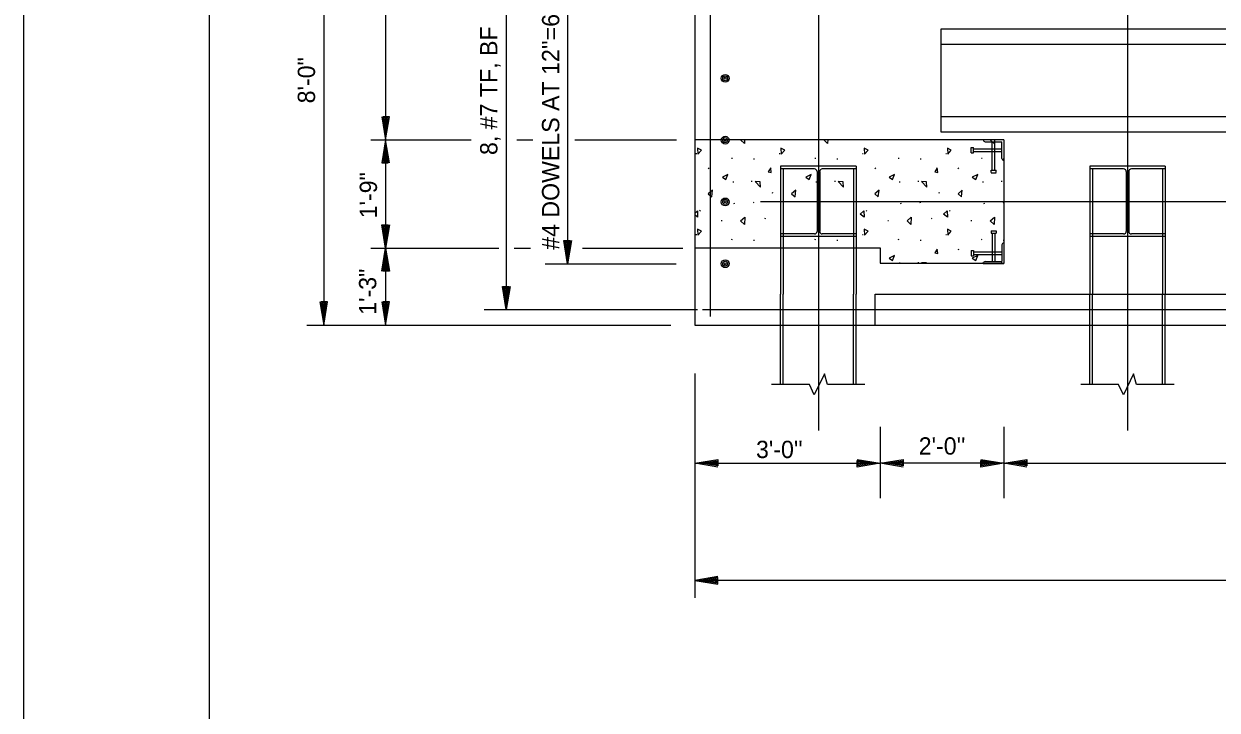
# Model space of a CAD drawing. Extents: x -11983 to -11903, y -13969.5 to -13913.5.
# Drawn here: x -11983.01 to -11963.71, y -13935.3 to -13924.19 of the extents above; entities that cross this region are included whole.
import ezdxf

# ---------------------------------------------------------------- set-up
doc = ezdxf.new("R2010")
doc.units = 0
for name, color, linetype in [('Level 1', 7, 'Continuous'), ('Level 2', 7, 'Continuous'), ('Level 22', 7, 'Continuous'), ('Level 25', 7, 'Continuous'), ('Level 3', 7, 'Continuous'), ('Level 44', 7, 'Continuous'), ('Level 50', 7, 'Continuous'), ('Level 6', 7, 'Continuous')]:
    doc.layers.add(name, color=color, linetype=linetype)

msp = doc.modelspace()

# ---------------------------------------------------------------- linework, layer by layer
at = {"layer": 'Level 1'}
for points in [[(-11983.012, -13913.481), (-11903.012, -13913.481), (-11903.012, -13969.481), (-11983.012, -13969.481)], [(-11980.012, -13914.481), (-11904.012, -13914.481), (-11904.012, -13968.481), (-11980.012, -13968.481)]]:
    msp.add_lwpolyline(points, close=True, dxfattribs=at)
at = {"layer": 'Level 2'}
for p, q in [((-11972.163, -13921.074), (-11972.163, -13929.066)), ((-11968.183, -13924.274), (-11942.163, -13924.274)), ((-11968.183, -13924.279), (-11968.183, -13925.941)), ((-11968.183, -13924.524), (-11942.122, -13924.524)), ((-11968.183, -13925.691), (-11942.122, -13925.691)), ((-11968.183, -13925.941), (-11942.163, -13925.941)), ((-11972.163, -13926.066), (-11967.163, -13926.066)), ((-11967.496, -13926.07), (-11967.496, -13926.07)), ((-11967.465, -13926.102), (-11967.195, -13926.102)), ((-11967.351, -13926.56), (-11967.351, -13926.102)), ((-11967.309, -13926.56), (-11967.309, -13926.102)), ((-11967.195, -13926.372), (-11967.195, -13926.102)), ((-11967.163, -13926.07), (-11967.163, -13928.066)), ((-11967.163, -13926.07), (-11967.163, -13926.403)), ((-11967.694, -13926.278), (-11967.694, -13926.195)), ((-11967.694, -13926.195), (-11967.653, -13926.195)), ((-11967.694, -13926.278), (-11967.653, -13926.278)), ((-11967.653, -13926.278), (-11967.653, -13926.195)), ((-11967.653, -13926.216), (-11967.195, -13926.216)), ((-11967.653, -13926.258), (-11967.195, -13926.258)), ((-11969.554, -13926.498), (-11970.773, -13926.498)), ((-11970.773, -13926.498), (-11970.773, -13926.54)), ((-11970.773, -13926.54), (-11970.773, -13928.566)), ((-11970.226, -13926.54), (-11970.773, -13926.54)), ((-11970.731, -13926.54), (-11970.731, -13928.566)), ((-11969.554, -13926.54), (-11970.101, -13926.54)), ((-11969.596, -13926.54), (-11969.596, -13928.566)), ((-11969.554, -13926.498), (-11969.554, -13926.54)), ((-11969.554, -13926.54), (-11969.554, -13928.566)), ((-11967.371, -13926.56), (-11967.288, -13926.56)), ((-11967.371, -13926.599), (-11967.371, -13926.56)), ((-11967.288, -13926.599), (-11967.288, -13926.56)), ((-11967.163, -13926.403), (-11967.163, -13926.403)), ((-11967.163, -13926.403), (-11967.163, -13927.737)), ((-11964.554, -13926.498), (-11965.773, -13926.498)), ((-11965.773, -13926.498), (-11965.773, -13926.54)), ((-11965.773, -13926.54), (-11965.773, -13928.566)), ((-11965.226, -13926.54), (-11965.773, -13926.54)), ((-11965.731, -13926.54), (-11965.731, -13928.566)), ((-11964.554, -13926.54), (-11965.101, -13926.54)), ((-11964.596, -13926.54), (-11964.596, -13928.566)), ((-11964.554, -13926.498), (-11964.554, -13926.54)), ((-11964.554, -13926.54), (-11964.554, -13928.566)), ((-11970.184, -13926.582), (-11970.184, -13927.55)), ((-11970.142, -13926.582), (-11970.142, -13927.55)), ((-11967.371, -13926.601), (-11967.288, -13926.601)), ((-11965.184, -13926.582), (-11965.184, -13927.55)), ((-11965.142, -13926.582), (-11965.142, -13927.55)), ((-11970.226, -13927.592), (-11970.773, -13927.592)), ((-11970.773, -13927.592), (-11970.773, -13927.634)), ((-11969.554, -13927.634), (-11970.773, -13927.634)), ((-11969.554, -13927.592), (-11970.101, -13927.592)), ((-11969.554, -13927.592), (-11969.554, -13927.634)), ((-11967.371, -13927.54), (-11967.288, -13927.54)), ((-11967.371, -13927.541), (-11967.371, -13927.581)), ((-11967.371, -13927.581), (-11967.288, -13927.581)), ((-11967.351, -13927.581), (-11967.351, -13928.039)), ((-11967.309, -13927.581), (-11967.309, -13928.039)), ((-11967.288, -13927.541), (-11967.288, -13927.581)), ((-11965.226, -13927.592), (-11965.773, -13927.592)), ((-11965.773, -13927.592), (-11965.773, -13927.634)), ((-11964.554, -13927.634), (-11965.773, -13927.634)), ((-11964.554, -13927.592), (-11965.101, -13927.592)), ((-11964.554, -13927.592), (-11964.554, -13927.634)), ((-11972.163, -13927.816), (-11969.163, -13927.816)), ((-11969.163, -13927.816), (-11969.163, -13928.066)), ((-11967.694, -13927.862), (-11967.694, -13927.945)), ((-11967.694, -13927.862), (-11967.653, -13927.862)), ((-11967.653, -13927.862), (-11967.653, -13927.945)), ((-11967.653, -13927.883), (-11967.195, -13927.883)), ((-11967.195, -13927.769), (-11967.195, -13928.039)), ((-11967.163, -13927.737), (-11967.163, -13927.737)), ((-11967.163, -13927.737), (-11967.163, -13928.07)), ((-11969.163, -13928.066), (-11967.163, -13928.066)), ((-11967.694, -13927.945), (-11967.653, -13927.945)), ((-11967.653, -13927.925), (-11967.195, -13927.925)), ((-11967.496, -13928.07), (-11967.496, -13928.07)), ((-11967.465, -13928.039), (-11967.195, -13928.039)), ((-11970.773, -13930.027), (-11970.773, -13928.566)), ((-11970.731, -13930.027), (-11970.731, -13928.566)), ((-11969.596, -13930.027), (-11969.596, -13928.566)), ((-11969.554, -13930.027), (-11969.554, -13928.566)), ((-11969.243, -13928.566), (-11957.178, -13928.566)), ((-11969.243, -13929.066), (-11969.243, -13928.566)), ((-11965.773, -13930.027), (-11965.773, -13928.566)), ((-11965.731, -13930.027), (-11965.731, -13928.566)), ((-11964.596, -13930.027), (-11964.596, -13928.566)), ((-11964.554, -13930.027), (-11964.554, -13928.566)), ((-11972.163, -13929.066), (-11957.178, -13929.066)), ((-11971.163, -13929.066), (-11965.413, -13929.066)), ((-11970.309, -13930.027), (-11970.919, -13930.027)), ((-11970.229, -13930.194), (-11970.309, -13930.027)), ((-11970.066, -13929.857), (-11970.229, -13930.194)), ((-11970.018, -13930.027), (-11970.066, -13929.857)), ((-11969.41, -13930.027), (-11970.018, -13930.027)), ((-11965.309, -13930.027), (-11965.919, -13930.027)), ((-11965.229, -13930.194), (-11965.309, -13930.027)), ((-11965.066, -13929.857), (-11965.229, -13930.194)), ((-11965.018, -13930.027), (-11965.066, -13929.857)), ((-11964.41, -13930.027), (-11965.018, -13930.027))]:
    msp.add_line(p, q, dxfattribs=at)
for centre, radius, start, end in [((-11967.465, -13926.07), 0.0312, 180, 270), ((-11967.163, -13926.372), 0.0312, 180, 270), ((-11970.226, -13926.582), 0.0417, 0, 90), ((-11970.101, -13926.582), 0.0417, 90, 180), ((-11965.226, -13926.582), 0.0417, 0, 90), ((-11965.101, -13926.582), 0.0417, 90, 180), ((-11970.226, -13927.55), 0.0417, 270, 0), ((-11970.101, -13927.55), 0.0417, 180, 270), ((-11965.226, -13927.55), 0.0417, 270, 0), ((-11965.101, -13927.55), 0.0417, 180, 270), ((-11967.163, -13927.769), 0.0312, 90, 180), ((-11967.465, -13928.07), 0.0312, 90, 180)]:
    msp.add_arc(centre, radius, start, end, dxfattribs=at)
at = {"layer": 'Level 22'}
for p, q in [((-11975.21, -13921.321), (-11975.21, -13928.814)), ((-11974.22, -13922.074), (-11974.22, -13928.074)), ((-11970.163, -13926.377), (-11970.163, -13927.066)), ((-11965.163, -13926.377), (-11965.163, -13927.066)), ((-11970.163, -13927.066), (-11970.163, -13927.857)), ((-11965.163, -13927.066), (-11965.163, -13927.857)), ((-11969.163, -13930.71), (-11969.163, -13931.868)), ((-11967.163, -13930.71), (-11967.163, -13931.868)), ((-11967.163, -13931.302), (-11969.163, -13931.302))]:
    msp.add_line(p, q, dxfattribs=at)
at = {"layer": 'Level 25'}
msp.add_line((-11967.496, -13928.07), (-11967.163, -13928.07), dxfattribs=at)
at = {"layer": 'Level 3'}
for p, q in [((-11978.163, -13921.074), (-11978.163, -13929.066)), ((-11977.163, -13921.074), (-11977.163, -13926.07)), ((-11970.163, -13923.074), (-11970.163, -13927.066)), ((-11965.163, -13923.074), (-11965.163, -13927.066)), ((-11977.163, -13924.57), (-11977.163, -13926.568)), ((-11977.163, -13925.966), (-11977.163, -13925.966)), ((-11977.403, -13926.07), (-11975.779, -13926.07)), ((-11977.163, -13926.07), (-11977.163, -13926.07)), ((-11977.163, -13926.07), (-11977.163, -13926.07)), ((-11977.163, -13926.07), (-11977.163, -13927.82)), ((-11977.163, -13926.174), (-11977.163, -13926.174)), ((-11975.042, -13926.07), (-11974.779, -13926.07)), ((-11974.102, -13926.07), (-11972.455, -13926.07)), ((-11971.099, -13927.066), (-11955.163, -13927.066)), ((-11970.163, -13927.066), (-11970.163, -13930.77)), ((-11970.163, -13927.066), (-11970.163, -13930.77)), ((-11965.163, -13927.066), (-11965.163, -13930.77)), ((-11977.403, -13927.82), (-11975.331, -13927.82)), ((-11977.163, -13927.82), (-11977.163, -13929.066)), ((-11975.085, -13927.82), (-11974.819, -13927.82)), ((-11973.975, -13927.82), (-11972.356, -13927.82)), ((-11974.581, -13928.074), (-11972.465, -13928.074)), ((-11975.567, -13928.814), (-11972.12, -13928.814)), ((-11978.435, -13929.066), (-11972.547, -13929.066)), ((-11978.163, -13928.962), (-11978.163, -13928.962)), ((-11978.163, -13929.066), (-11978.163, -13929.066)), ((-11977.163, -13928.962), (-11977.163, -13928.962)), ((-11977.163, -13929.066), (-11977.163, -13929.066)), ((-11972.163, -13929.85), (-11972.163, -13932.694)), ((-11972.163, -13930.824), (-11972.163, -13933.48)), ((-11972.163, -13931.302), (-11969.163, -13931.302)), ((-11967.163, -13931.302), (-11943.125, -13931.302)), ((-11938.163, -13933.196), (-11972.163, -13933.196)), ((-11972.163, -13933.196), (-11972.163, -13933.196)), ((-11972.059, -13933.196), (-11972.059, -13933.196))]:
    msp.add_line(p, q, dxfattribs=at)
for points in [[(-11977.225, -13925.696), (-11977.163, -13926.07), (-11977.101, -13925.696), (-11977.207, -13925.696), (-11977.163, -13925.966), (-11977.121, -13925.712), (-11977.189, -13925.712), (-11977.163, -13925.866), (-11977.141, -13925.728), (-11977.169, -13925.728), (-11977.163, -13925.762)], [(-11977.101, -13926.444), (-11977.163, -13926.07), (-11977.225, -13926.444), (-11977.119, -13926.444), (-11977.163, -13926.174), (-11977.205, -13926.428), (-11977.137, -13926.428), (-11977.163, -13926.274), (-11977.185, -13926.412), (-11977.157, -13926.412), (-11977.163, -13926.378)], [(-11978.225, -13928.692), (-11978.163, -13929.066), (-11978.101, -13928.692), (-11978.207, -13928.692), (-11978.163, -13928.962), (-11978.121, -13928.708), (-11978.189, -13928.708), (-11978.163, -13928.862), (-11978.141, -13928.724), (-11978.169, -13928.724), (-11978.163, -13928.758)], [(-11977.225, -13928.692), (-11977.163, -13929.066), (-11977.101, -13928.692), (-11977.207, -13928.692), (-11977.163, -13928.962), (-11977.121, -13928.708), (-11977.189, -13928.708), (-11977.163, -13928.862), (-11977.141, -13928.724), (-11977.169, -13928.724), (-11977.163, -13928.758)], [(-11971.789, -13933.134), (-11972.163, -13933.196), (-11971.789, -13933.258), (-11971.789, -13933.152), (-11972.059, -13933.196), (-11971.805, -13933.238), (-11971.805, -13933.17), (-11971.959, -13933.196), (-11971.821, -13933.218), (-11971.821, -13933.19), (-11971.855, -13933.196)]]:
    msp.add_lwpolyline(points, dxfattribs=at)
at = {"layer": 'Level 44'}
for p, q in [((-11971.721, -13926.068), (-11971.735, -13926.07)), ((-11970.374, -13926.068), (-11970.389, -13926.07)), ((-11967.681, -13926.068), (-11967.695, -13926.07)), ((-11972.13, -13926.295), (-11972.143, -13926.294)), ((-11971.552, -13926.373), (-11971.566, -13926.371)), ((-11970.783, -13926.295), (-11970.797, -13926.294)), ((-11970.206, -13926.373), (-11970.219, -13926.371)), ((-11969.437, -13926.295), (-11969.45, -13926.294)), ((-11968.859, -13926.373), (-11968.872, -13926.371)), ((-11968.09, -13926.295), (-11968.103, -13926.294)), ((-11967.548, -13926.22), (-11967.566, -13926.22)), ((-11967.512, -13926.373), (-11967.526, -13926.371)), ((-11971.93, -13926.53), (-11971.946, -13926.538)), ((-11971.194, -13926.385), (-11971.212, -13926.385)), ((-11969.847, -13926.385), (-11969.865, -13926.385)), ((-11969.236, -13926.53), (-11969.252, -13926.538)), ((-11968.5, -13926.385), (-11968.518, -13926.385)), ((-11967.89, -13926.53), (-11967.906, -13926.538)), ((-11967.163, -13926.385), (-11967.172, -13926.385)), ((-11971.531, -13926.752), (-11971.549, -13926.752)), ((-11971.232, -13926.745), (-11971.249, -13926.745)), ((-11970.184, -13926.752), (-11970.202, -13926.752)), ((-11969.886, -13926.745), (-11969.903, -13926.745)), ((-11968.838, -13926.752), (-11968.856, -13926.752)), ((-11968.539, -13926.745), (-11968.556, -13926.745)), ((-11967.491, -13926.752), (-11967.509, -13926.752)), ((-11967.192, -13926.745), (-11967.209, -13926.745)), ((-11970.893, -13926.932), (-11970.91, -13926.929)), ((-11968.2, -13926.932), (-11968.217, -13926.929)), ((-11971.517, -13927.101), (-11971.535, -13927.106)), ((-11971.206, -13927.083), (-11971.219, -13927.088)), ((-11968.823, -13927.101), (-11968.841, -13927.106)), ((-11968.513, -13927.083), (-11968.526, -13927.088)), ((-11967.477, -13927.101), (-11967.495, -13927.106)), ((-11967.166, -13927.083), (-11967.179, -13927.088)), ((-11972.07, -13927.224), (-11972.085, -13927.215)), ((-11969.377, -13927.224), (-11969.392, -13927.215)), ((-11968.03, -13927.224), (-11968.045, -13927.215)), ((-11971.721, -13927.38), (-11971.735, -13927.381)), ((-11971.014, -13927.348), (-11971.028, -13927.341)), ((-11969.027, -13927.38), (-11969.042, -13927.381)), ((-11968.32, -13927.348), (-11968.335, -13927.341)), ((-11967.681, -13927.38), (-11967.695, -13927.381)), ((-11972.13, -13927.607), (-11972.143, -13927.606)), ((-11971.552, -13927.685), (-11971.566, -13927.683)), ((-11971.194, -13927.696), (-11971.212, -13927.696)), ((-11970.206, -13927.685), (-11970.219, -13927.683)), ((-11969.847, -13927.696), (-11969.865, -13927.696)), ((-11969.437, -13927.607), (-11969.45, -13927.606)), ((-11968.859, -13927.685), (-11968.872, -13927.683)), ((-11968.5, -13927.696), (-11968.518, -13927.696)), ((-11968.09, -13927.607), (-11968.103, -13927.606)), ((-11967.512, -13927.685), (-11967.526, -13927.683)), ((-11967.163, -13927.696), (-11967.172, -13927.696)), ((-11967.89, -13927.842), (-11967.906, -13927.85)), ((-11968.838, -13928.063), (-11968.856, -13928.063)), ((-11968.539, -13928.057), (-11968.556, -13928.057)), ((-11967.491, -13928.063), (-11967.509, -13928.063)), ((-11967.192, -13928.057), (-11967.209, -13928.057))]:
    msp.add_line(p, q, dxfattribs=at)
for points in [[(-11971.357, -13926.066), (-11971.36, -13926.127), (-11971.422, -13926.07), (-11971.417, -13926.066)], [(-11970.01, -13926.066), (-11970.014, -13926.127), (-11970.075, -13926.07), (-11970.071, -13926.066)], [(-11967.317, -13926.066), (-11967.32, -13926.127), (-11967.382, -13926.07), (-11967.377, -13926.066)], [(-11972.163, -13927.254), (-11972.12, -13927.216), (-11972.117, -13927.318), (-11972.163, -13927.284)], [(-11968.414, -13928.066), (-11968.414, -13928.061), (-11968.494, -13928.057), (-11968.485, -13928.066)]]:
    msp.add_lwpolyline(points, dxfattribs=at)
for points in [[(-11972.111, -13926.3), (-11972.054, -13926.236), (-11972.117, -13926.202)], [(-11970.764, -13926.3), (-11970.707, -13926.236), (-11970.771, -13926.202)], [(-11969.417, -13926.3), (-11969.36, -13926.236), (-11969.424, -13926.202)], [(-11968.071, -13926.3), (-11968.014, -13926.236), (-11968.077, -13926.202)], [(-11970.924, -13926.598), (-11970.934, -13926.525), (-11970.975, -13926.586)], [(-11968.231, -13926.598), (-11968.24, -13926.525), (-11968.281, -13926.586)], [(-11971.657, -13926.713), (-11971.625, -13926.631), (-11971.714, -13926.674)], [(-11971.107, -13926.75), (-11971.187, -13926.745), (-11971.101, -13926.834)], [(-11970.31, -13926.713), (-11970.279, -13926.631), (-11970.367, -13926.674)], [(-11969.761, -13926.75), (-11969.841, -13926.745), (-11969.754, -13926.834)], [(-11968.964, -13926.713), (-11968.932, -13926.631), (-11969.02, -13926.674)], [(-11968.414, -13926.75), (-11968.494, -13926.745), (-11968.407, -13926.834)], [(-11967.617, -13926.713), (-11967.585, -13926.631), (-11967.674, -13926.674)], [(-11971.876, -13926.884), (-11971.944, -13926.943), (-11971.887, -13926.991)], [(-11970.529, -13926.884), (-11970.597, -13926.943), (-11970.541, -13926.991)], [(-11969.182, -13926.884), (-11969.251, -13926.943), (-11969.194, -13926.991)], [(-11967.836, -13926.884), (-11967.904, -13926.943), (-11967.847, -13926.991)], [(-11971.36, -13927.439), (-11971.422, -13927.382), (-11971.354, -13927.321)], [(-11969.424, -13927.318), (-11969.488, -13927.27), (-11969.427, -13927.216)], [(-11968.667, -13927.439), (-11968.729, -13927.382), (-11968.66, -13927.321)], [(-11968.077, -13927.318), (-11968.141, -13927.27), (-11968.08, -13927.216)], [(-11967.32, -13927.439), (-11967.382, -13927.382), (-11967.314, -13927.321)], [(-11972.111, -13927.612), (-11972.054, -13927.548), (-11972.117, -13927.514)], [(-11969.417, -13927.612), (-11969.36, -13927.548), (-11969.424, -13927.514)], [(-11968.071, -13927.612), (-11968.014, -13927.548), (-11968.077, -13927.514)], [(-11968.231, -13927.91), (-11968.24, -13927.837), (-11968.281, -13927.898)], [(-11968.964, -13928.024), (-11968.932, -13927.943), (-11969.02, -13927.986)], [(-11967.617, -13928.024), (-11967.585, -13927.943), (-11967.674, -13927.986)]]:
    msp.add_lwpolyline(points, close=True, dxfattribs=at)
at = {"layer": 'Level 50'}
for p, q in [((-11977.163, -13927.716), (-11977.163, -13927.716)), ((-11977.163, -13927.82), (-11977.163, -13927.82)), ((-11977.163, -13927.82), (-11977.163, -13927.82)), ((-11977.163, -13927.924), (-11977.163, -13927.924)), ((-11974.22, -13927.97), (-11974.22, -13927.97)), ((-11974.22, -13928.074), (-11974.22, -13928.074)), ((-11975.21, -13928.71), (-11975.21, -13928.71)), ((-11975.21, -13928.814), (-11975.21, -13928.814)), ((-11972.163, -13931.302), (-11972.163, -13931.302)), ((-11972.059, -13931.302), (-11972.059, -13931.302)), ((-11969.267, -13931.302), (-11969.267, -13931.302)), ((-11969.163, -13931.302), (-11969.163, -13931.302)), ((-11969.163, -13931.302), (-11969.163, -13931.302)), ((-11969.059, -13931.302), (-11969.059, -13931.302)), ((-11967.267, -13931.302), (-11967.267, -13931.302)), ((-11967.163, -13931.302), (-11967.163, -13931.302)), ((-11967.163, -13931.302), (-11967.163, -13931.302)), ((-11967.059, -13931.302), (-11967.059, -13931.302))]:
    msp.add_line(p, q, dxfattribs=at)
for points in [[(-11977.101, -13927.446), (-11977.163, -13927.82), (-11977.225, -13927.446), (-11977.119, -13927.446), (-11977.163, -13927.716), (-11977.205, -13927.462), (-11977.137, -13927.462), (-11977.163, -13927.616), (-11977.185, -13927.478), (-11977.157, -13927.478), (-11977.163, -13927.512)], [(-11974.158, -13927.7), (-11974.22, -13928.074), (-11974.282, -13927.7), (-11974.176, -13927.7), (-11974.22, -13927.97), (-11974.262, -13927.716), (-11974.194, -13927.716), (-11974.22, -13927.87), (-11974.242, -13927.732), (-11974.214, -13927.732), (-11974.22, -13927.766)], [(-11977.225, -13928.194), (-11977.163, -13927.82), (-11977.101, -13928.194), (-11977.207, -13928.194), (-11977.163, -13927.924), (-11977.121, -13928.178), (-11977.189, -13928.178), (-11977.163, -13928.024), (-11977.141, -13928.162), (-11977.169, -13928.162), (-11977.163, -13928.128)], [(-11975.148, -13928.44), (-11975.21, -13928.814), (-11975.272, -13928.44), (-11975.166, -13928.44), (-11975.21, -13928.71), (-11975.252, -13928.456), (-11975.184, -13928.456), (-11975.21, -13928.61), (-11975.232, -13928.472), (-11975.204, -13928.472), (-11975.21, -13928.506)], [(-11971.789, -13931.364), (-11972.163, -13931.302), (-11971.789, -13931.24), (-11971.789, -13931.346), (-11972.059, -13931.302), (-11971.805, -13931.26), (-11971.805, -13931.328), (-11971.959, -13931.302), (-11971.821, -13931.28), (-11971.821, -13931.308), (-11971.855, -13931.302)], [(-11969.537, -13931.24), (-11969.163, -13931.302), (-11969.537, -13931.364), (-11969.537, -13931.258), (-11969.267, -13931.302), (-11969.521, -13931.344), (-11969.521, -13931.276), (-11969.367, -13931.302), (-11969.505, -13931.324), (-11969.505, -13931.296), (-11969.471, -13931.302)], [(-11968.789, -13931.364), (-11969.163, -13931.302), (-11968.789, -13931.24), (-11968.789, -13931.346), (-11969.059, -13931.302), (-11968.805, -13931.26), (-11968.805, -13931.328), (-11968.959, -13931.302), (-11968.821, -13931.28), (-11968.821, -13931.308), (-11968.855, -13931.302)], [(-11967.537, -13931.24), (-11967.163, -13931.302), (-11967.537, -13931.364), (-11967.537, -13931.258), (-11967.267, -13931.302), (-11967.521, -13931.344), (-11967.521, -13931.276), (-11967.367, -13931.302), (-11967.505, -13931.324), (-11967.505, -13931.296), (-11967.471, -13931.302)], [(-11966.789, -13931.364), (-11967.163, -13931.302), (-11966.789, -13931.24), (-11966.789, -13931.346), (-11967.059, -13931.302), (-11966.805, -13931.26), (-11966.805, -13931.328), (-11966.959, -13931.302), (-11966.821, -13931.28), (-11966.821, -13931.308), (-11966.855, -13931.302)]]:
    msp.add_lwpolyline(points, dxfattribs=at)
at = {"layer": 'Level 6'}
for p, q in [((-11971.914, -13921.193), (-11971.914, -13928.927)), ((-11972.035, -13928.816), (-11957.178, -13928.816))]:
    msp.add_line(p, q, dxfattribs=at)
for centre, radius in [((-11971.67, -13925.074), 0.0633), ((-11971.67, -13925.074), 0.0396), ((-11971.67, -13925.074), 0.0158), ((-11971.67, -13926.074), 0.0633), ((-11971.67, -13926.074), 0.0396), ((-11971.67, -13926.074), 0.0158), ((-11971.67, -13927.074), 0.0633), ((-11971.67, -13927.074), 0.0396), ((-11971.67, -13927.074), 0.0158), ((-11971.67, -13928.074), 0.0633), ((-11971.67, -13928.074), 0.0396), ((-11971.67, -13928.074), 0.0158)]:
    msp.add_circle(centre, radius, dxfattribs=at)

# ---------------------------------------------------------------- texts
at = {"layer": 'Level 3'}
for s, p in [("#4 DOWELS AT 12''=6'-0''", (-11974.353, -13927.849)), ('8, #7 TF, BF', (-11975.354, -13926.315)), ('8\'-0"', (-11978.303, -13925.479)), ('1\'-9"', (-11977.301, -13927.339)), ('1\'-3"', (-11977.313, -13928.9))]:
    msp.add_text(s, height=0.28, rotation=90, dxfattribs=at).set_placement(p)
for s, p in [("3'-0''", (-11971.172, -13931.218)), ("2'-0'' ", (-11968.54, -13931.162))]:
    msp.add_text(s, height=0.28, dxfattribs=at).set_placement(p)

doc.saveas('drawing.dxf')
